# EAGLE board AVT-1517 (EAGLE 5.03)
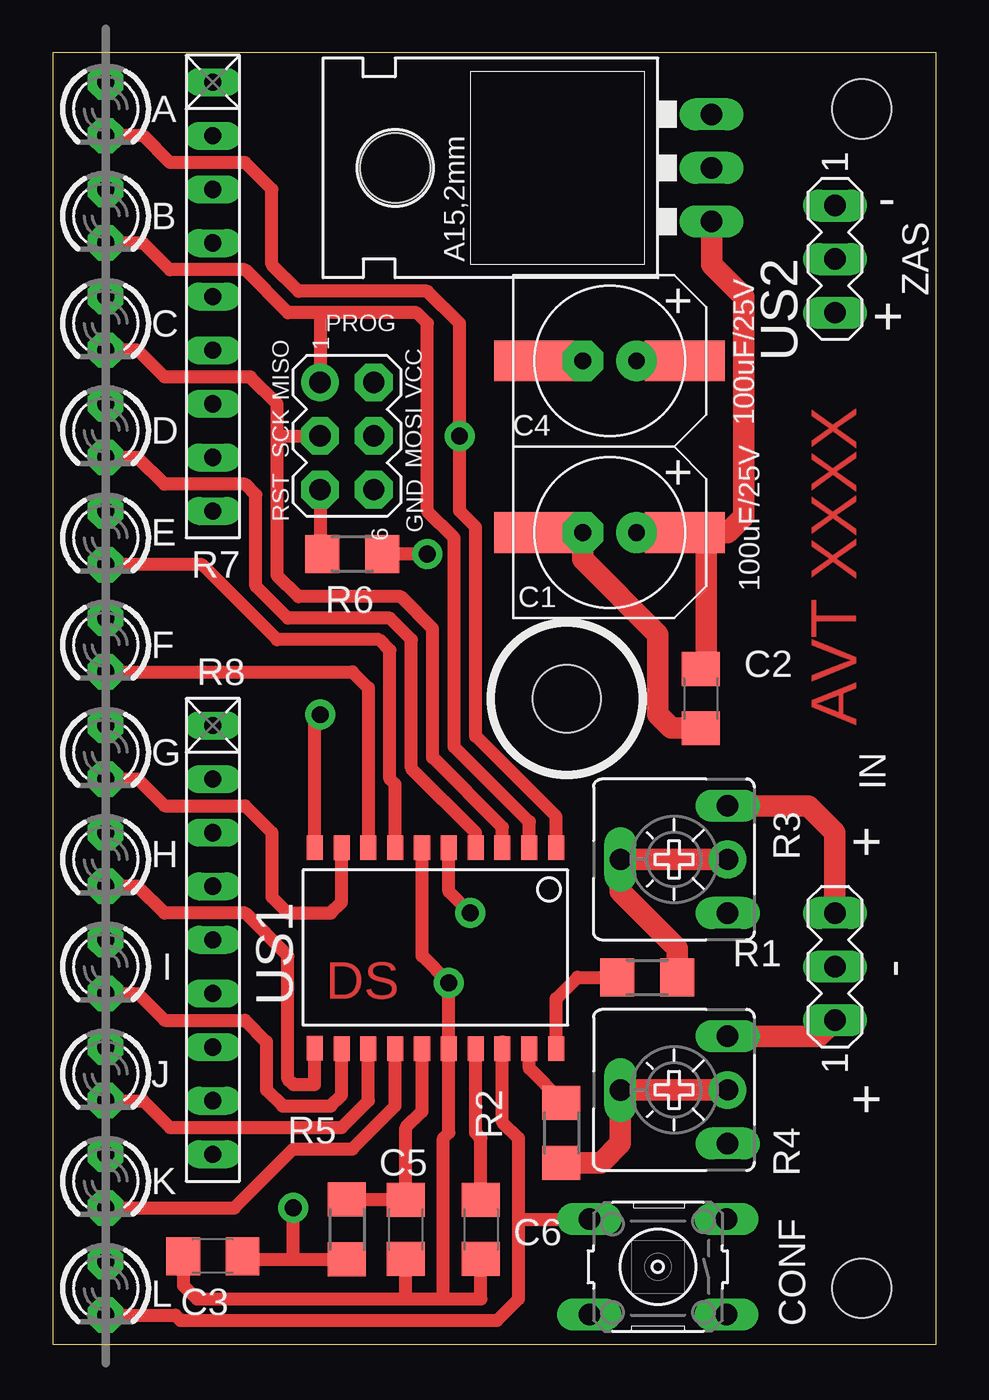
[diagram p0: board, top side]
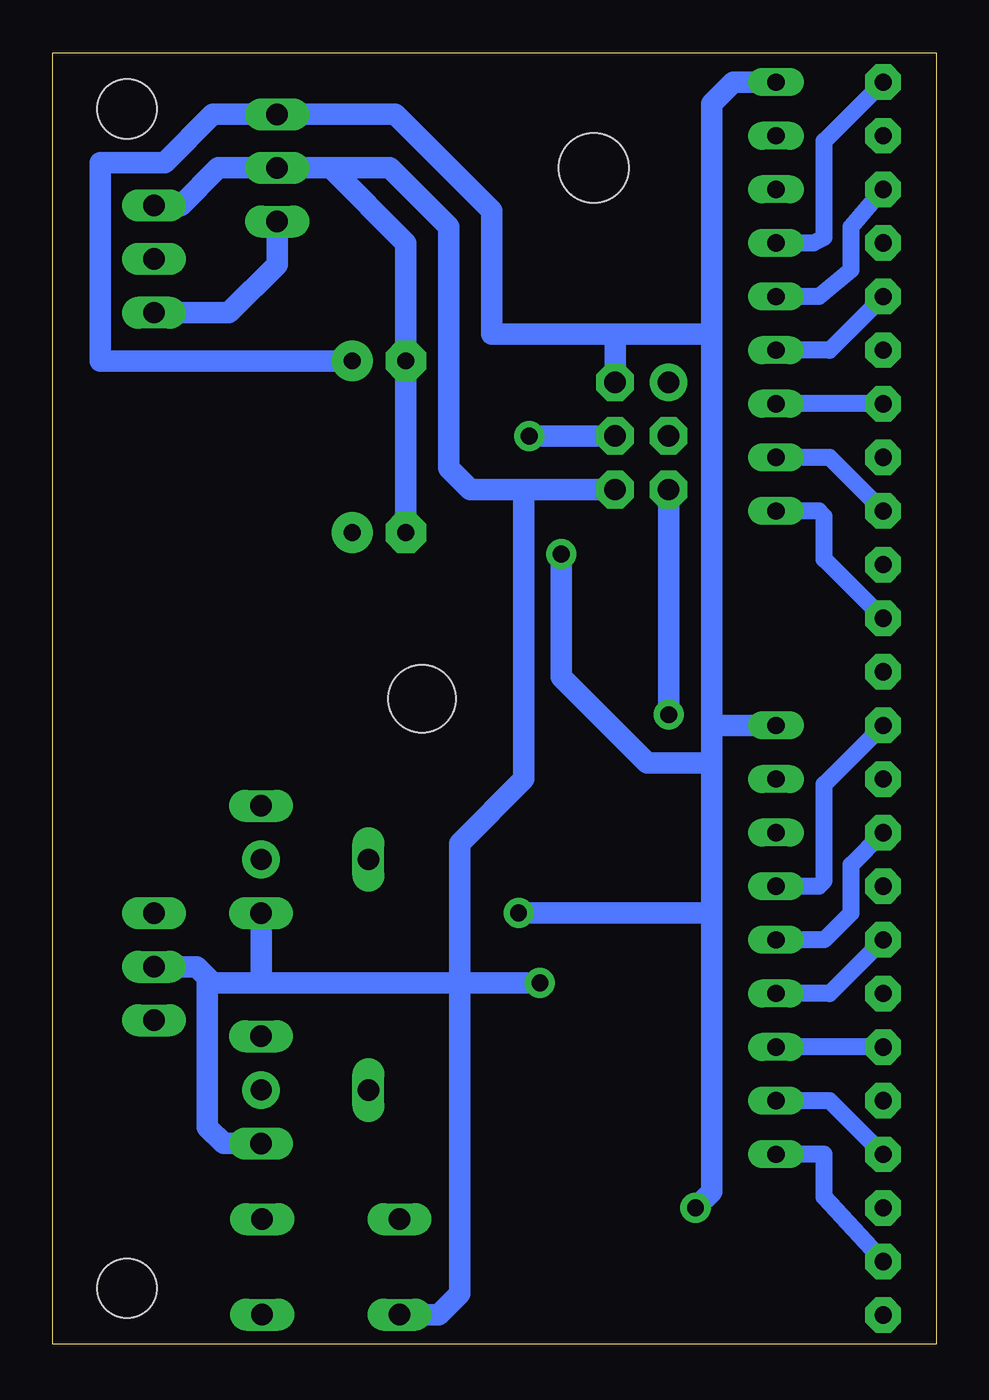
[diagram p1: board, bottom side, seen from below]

Size 41.83 x 61.2 mm. Coordinates in mm from the lower left corner, seen from the top.
Outline: 0,0 41.83,0 41.83,61.2 0,61.2 0,0
Copper layers (1*16): Top 0.035mm / dielectric 1.5mm / Bottom 0.035mm
Design rules "default": minimum track width 10mil, minimum drill 24mil, track to track 8mil, track to pad 8mil, pad to pad 8mil, via to via 8mil, smd to smd 8mil, copper to edge 40mil, drill to drill 8mil, minimum pad ring 10mil, minimum via ring 8mil, stop-mask expansion 4mil, vias tented up to drill 0mil, thermal gap 10mil
Holes 2.8 mm at 38.32,58.54 38.32,2.66
Holes 3.2 mm at 24.35,30.6

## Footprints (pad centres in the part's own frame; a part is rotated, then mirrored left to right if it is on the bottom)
LED3MM = drill 0.813 pad 1.676 octagon: A -1.27,0; K 1.27,0
MULTI_CAP = smd 3.81 x 1.93: 1 3.556,0; 2 -3.556,0 | drill 0.8 pad 1.93 octagon: 3 -1.27,0 | drill 0.8 pad 1.93 round: 4 1.27,0
C1206 = smd 1.6 x 1.8: 1 -1.4,0; 2 1.4,0
B3F-10XX = drill 1.016 long: 1 -3.251,2.261; 2 3.251,2.261; 3 -3.251,-2.261; 4 3.251,-2.261
MA03-1 = drill 1.016 long: 1 -2.54,0; 2 0,0; 3 2.54,0
MA03-2 = drill 1.016 pad 1.778 round: 1 -2.54,-1.27 | drill 1.016 pad 1.778 octagon: 2 -2.54,1.27; 3 0,-1.27; 4 0,1.27; 5 2.54,-1.27; 6 2.54,1.27
R1206 = smd 1.6 x 1.803: 1 -1.422,0; 2 1.422,0
CA6V = drill 1.016 long: A -2.54,-2.54; E 2.54,-2.54; S 0,2.54
RN-9 = drill 0.813 long: 1 -10.16,0; 2 -7.62,0; 3 -5.08,0; 4 -2.54,0; 5 0,0; 6 2.54,0; 7 5.08,0; 8 7.62,0; 9 10.16,0
SO20L = smd 0.762 x 1.143: 1 -5.08,-5.131; 2 -3.81,-5.131; 3 -2.54,-5.131; 4 -1.27,-5.131; 5 0,-5.131; 6 1.27,-5.131; 7 2.54,-5.131; 8 3.81,-5.131; 9 5.08,-5.131; 10 6.35,-5.131; 11 6.35,4.369; 12 5.08,4.394; 13 3.81,4.394; 14 2.54,4.394; 15 1.27,4.394; 16 0,4.394; 17 -1.27,4.394; 18 -2.54,4.394; 19 -3.81,4.394; 20 -5.08,4.394
78XXL = drill 1.016 long: GND 0,-3.81; IN -2.54,-3.81; OUT 2.54,-3.81 | hole 3.302: 0,11.176

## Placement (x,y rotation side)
A  [LED3MM]  2.5,58.54 270 top
B  [LED3MM]  2.5,53.46 270 top
C  [LED3MM]  2.5,48.38 270 top
C1  100uF/25V  [MULTI_CAP]  26.38,38.48 0 top
C2  100n  [C1206]  30.7,30.6 270 top
C3  100n  [C1206]  7.58,4.19 180 top
C4  100uF/25V  [MULTI_CAP]  26.38,46.6 0 top
C5  10uF/16V  [C1206]  16.73,5.46 90 top
C6  100n  [C1206]  20.28,5.46 270 top
CONF  [B3F-10XX]  28.66,3.68 180 top
D  [LED3MM]  2.5,43.3 270 top
E  [LED3MM]  2.5,38.22 270 top
F  [LED3MM]  2.5,33.14 270 top
G  [LED3MM]  2.5,28.06 270 top
H  [LED3MM]  2.5,22.98 270 top
I  [LED3MM]  2.5,17.9 270 top
IN  [MA03-1]  37.05,17.9 90 top
J  [LED3MM]  2.5,12.82 270 top
K  [LED3MM]  2.5,7.74 270 top
L  [LED3MM]  2.5,2.66 270 top
PROG  [MA03-2]  13.93,43.05 270 top
R1  10k  [R1206]  28.16,17.39 180 top
R2  10k  [R1206]  24.09,10.03 90 top
R3  10k  [CA6V]  29.43,22.98 90 top
R4  10k  [CA6V]  29.43,12.06 90 top
R5  10R  [R1206]  13.93,5.46 90 top
R6  10k  [R1206]  14.19,37.46 180 top
R7  8x470R  [RN-9]  7.58,49.65 270 top
R8  8x470R  [RN-9]  7.58,19.17 270 top
US1  TINY26S  [SO20L]  18.76,18.41 180 top
US2  LM2940  [78XXL]  27.39,55.75 90 top
ZAS  [MA03-1]  37.05,51.43 270 top

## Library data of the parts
A B C D E F G H I J K L = led
C1-C6 R1 R2 R5 R6 = rcl
CONF = switch-omron
IN PROG ZAS = con-lstb
R3 R4 = pot
R7 R8 = resistor-net
US1 = atmel
US2 = v-reg

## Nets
+5V: C3.1 C4.4 PROG.2 R5.1 R6.1 R7.1 R8.1 US1.5 US2.OUT
A: A.K PROG.4 US1.1
B: B.K PROG.1 US1.2
C: C.K PROG.3 US1.3
D: D.K US1.4
E: E.K US1.7
F: F.K US1.8
G: G.K US1.9
GND: C1.3 C2.2 C3.2 C4.3 C5.1 C6.2 CONF.2 IN.2 PROG.6 R3.A R4.A US1.6 US1.16 US2.GND ZAS.1
H: H.K US1.11
I: I.K US1.12
J: J.K US1.13
K: K.K US1.14
L: CONF.4 L.K US1.18
N$1: A.A R7.4
N$2: IN.3 R3.E
N$3: C1.4 C2.1 US2.IN ZAS.3
N$4: IN.1 R4.E
N$5: K.A R8.8
N$6: PROG.5 R6.2 US1.10
N$8: R1.1 R3.S
N$10: B.A R7.5
N$11: R2.1 R4.S
N$13: C.A R7.6
N$14: D.A R7.7
N$15: E.A R7.8
N$16: F.A R7.9
N$17: G.A R8.4
N$18: H.A R8.5
N$19: I.A R8.6
N$20: J.A R8.7
N$21: L.A R8.9
N$23: R1.2 US1.20
N$24: R2.2 US1.19
N$25: C6.1 US1.17
N$27: C5.2 R5.2 US1.15

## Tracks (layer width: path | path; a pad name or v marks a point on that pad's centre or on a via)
+5V  (via drill 0.8 pad 1.42)
  Top 0.61: v17.74,37.46 R6.1 | v19.77,20.44 18.76,21.46 US1.5 | C3.1 9.11,4.19 9.26,4.03 11.39,4.03 | 11.39,4.03 R5.1 | 11.39,4.03 v11.39,6.47
  Bottom 1.016: 10.63,29.33 R8.1 | 10.63,29.33 10.63,47.87 | 15.2,47.87 PROG.2 | 10.63,27.55 10.63,29.33 | 10.63,47.87 15.2,47.87 | v17.74,37.46 17.74,31.62 13.68,27.55 10.63,27.55 | 10.63,20.44 10.63,27.55 | 10.63,20.44 v19.77,20.44 | 10.63,20.44 10.63,7.23 v11.39,6.47 | C4.4 39.59,46.6 39.59,56 36.54,56 34.25,58.29 US2.OUT 25.62,58.29 21.04,53.72 21.04,47.87 15.2,47.87 | 10.63,47.87 10.63,58.8 9.61,59.81 R7.1
A  (via drill 0.8 pad 1.42)
  Top 0.61: A.K 4.28,57.27 5.55,56 9.11,56 10.38,54.73 10.38,51.18 11.65,49.91 17.74,49.91 19.27,48.38 v19.27,43.05 19.27,39.49 20.03,38.73 20.03,28.82 23.84,25.01 US1.1
  Bottom 1.016: v19.27,43.05 PROG.4
B
  Top 0.61: B.K 4.28,52.19 5.55,50.92 9.11,50.92 11.14,48.89 12.66,48.89 | 12.66,48.89 17.23,48.89 17.74,48.38 17.74,39.49 19.01,38.22 19.01,28.32 22.57,24.76 US1.2 | 12.66,48.89 PROG.1
C
  Top 0.61: C.K 4.03,47.11 5.3,45.84 9.36,45.84 10.63,44.57 10.63,43.05 | 10.63,43.05 10.63,36.44 11.65,35.43 16.47,35.43 18,33.9 18,27.81 21.3,24.51 US1.3 | 10.63,43.05 PROG.3
D
  Top 0.61: D.K 4.03,42.03 5.3,40.76 9.11,40.76 9.61,40.25 9.61,35.94 11.14,34.41 15.96,34.41 16.98,33.4 16.98,27.3 20.03,24.25 US1.4
E
  Top 0.61: E.K 7.07,36.95 10.63,33.4 15.46,33.4 15.96,32.89 15.96,26.79 16.22,26.54 US1.7 16.22,23.49
F
  Top 0.61: F.K 14.19,31.87 14.95,31.11 US1.8 14.95,23.49
G
  Top 0.61: G.K 4.03,26.79 5.3,25.52 9.11,25.52 10.38,24.25 10.38,21.2 11.14,20.44 13.17,20.44 13.68,20.95 US1.9
GND  (via drill 0.8 pad 1.42)
  Top 0.61: C3.2 6.18,2.79 6.82,2.15 16.73,2.15 | 16.73,2.15 18.5,2.15 | 18.5,2.15 20.28,2.15 C6.2 20.03,4.19 | 16.73,2.15 C5.1 | 18.5,2.15 18.5,9.77 18.76,10.03 US1.16 v18.76,17.14 17.49,18.41 US1.6
  Top 1.016: C2.2 29.3,29.2 28.66,29.84 28.66,33.65 25.11,37.21 C1.3
  Bottom 1.016: 19.52,40.51 PROG.6 | 19.52,40.51 19.52,26.79 22.57,23.74 22.57,17.14 | v18.76,17.14 22.57,17.14 | CONF.2 23.56,1.42 22.57,2.41 22.57,17.14 | 31.97,17.14 R3.A | 22.57,17.14 31.97,17.14 | 31.97,17.14 34.25,17.14 | 34.25,17.14 34.51,17.14 34.51,10.28 33.74,9.52 R4.A | 28.66,55.75 US2.GND 34,55.75 35.78,53.97 ZAS.1 | 19.52,40.51 22.06,40.51 23.08,41.52 23.08,52.95 25.87,55.75 28.66,55.75 | C4.3 C1.3 C4.3 | IN.2 35.01,17.9 34.25,17.14 | C4.3 25.11,52.19 28.66,55.75
H
  Top 0.61: H.K 4.03,21.71 5.3,20.44 9.11,20.44 11.14,18.41 11.14,12.57 11.39,12.31 12.41,12.31 US1.11
I
  Top 0.61: I.K 4.03,16.63 5.3,15.36 9.11,15.36 10.12,14.35 10.12,12.06 10.88,11.3 13.17,11.3 13.68,11.81 US1.12
J
  Top 0.61: J.K 4.28,11.55 5.55,10.28 13.68,10.28 14.95,11.55 US1.13
K
  Top 0.61: K.K 8.6,6.47 11.39,9.27 14.19,9.27 16.22,11.3 US1.14
L
  Top 0.61: L.K 5.8,1.39 6.06,1.14 21.04,1.14 22.06,2.15 22.06,5.96 | 22.06,5.96 22.06,9.77 21.3,10.54 US1.18 21.3,14.35 | CONF.4 22.09,5.94 22.06,5.96
N$1
  Bottom 0.813: R7.4 5.8,52.19 5.3,52.45 5.3,57.02 A.A
N$2
  Top 1.016: IN.3 37.05,24.25 35.78,25.52 R3.E
N$3
  Top 1.016: US2.IN 31.2,51.18 32.73,49.65 32.73,39.24 31.97,38.48 30.95,38.48 | 30.95,38.48 C1.4 | C2.1 30.7,32.13 30.95,32.38 30.95,38.48
  Bottom 1.016: US2.IN 31.2,51.18 33.49,48.89 ZAS.3
N$4
  Top 1.016: R4.E 36.28,14.6 IN.1
N$5
  Bottom 0.813: R8.8 5.04,11.55 K.A
N$6  (via drill 0.8 pad 1.42)
  Top 0.61: 12.76,37.36 12.92,37.21 | 12.76,37.36 R6.2 | PROG.5 12.66,37.46 12.76,37.36 | US1.10 12.41,29.59 v12.66,29.84
  Bottom 1.016: v12.66,29.84 PROG.5
N$8  (via drill 1 pad 1.78)
  Top 1.016: R1.1 29.58,18.77 26.89,21.46 R3.S v31.97,22.98
N$10
  Bottom 0.813: R7.5 5.55,49.65 4.03,50.92 4.03,52.95 B.A
N$11  (via drill 1 pad 1.78)
  Top 1.016: R2.1 25.97,8.61 26.89,9.52 R4.S v31.97,12.06
N$13
  Bottom 0.813: R7.6 5.04,47.11 C.A
N$14
  Bottom 0.813: D.A R7.7
N$15
  Bottom 0.813: R7.8 5.04,42.03 E.A
N$16
  Bottom 0.813: R7.9 5.55,39.49 5.3,39.24 5.3,37.21 F.A
N$17
  Bottom 0.813: R8.4 5.55,21.71 5.3,21.97 5.3,26.54 G.A
N$18
  Bottom 0.813: R8.5 5.3,19.17 4.03,20.44 4.03,22.73 H.A
N$19
  Bottom 0.813: R8.6 5.04,16.63 I.A
N$20
  Bottom 0.813: J.A R8.7
N$21
  Bottom 0.813: R8.9 5.3,9.01 5.3,6.98 L.A
N$23
  Top 0.61: R1.2 24.85,17.39 23.84,16.38 US1.20
N$24
  Top 0.61: R2.2 24.09,11.55 22.57,13.08 US1.19
N$25
  Top 0.61: US1.17 20.03,10.03 20.28,9.77 C6.1 20.28,6.73
N$27
  Top 0.61: C5.2 16.73,6.98 16.62,6.88 R5.2 | US1.15 17.49,11.04 16.73,10.28 C5.2 | C5.2 16.73,6.47

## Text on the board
Top: AVT XXXX | DS
tPlace: - | + | + | - | +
